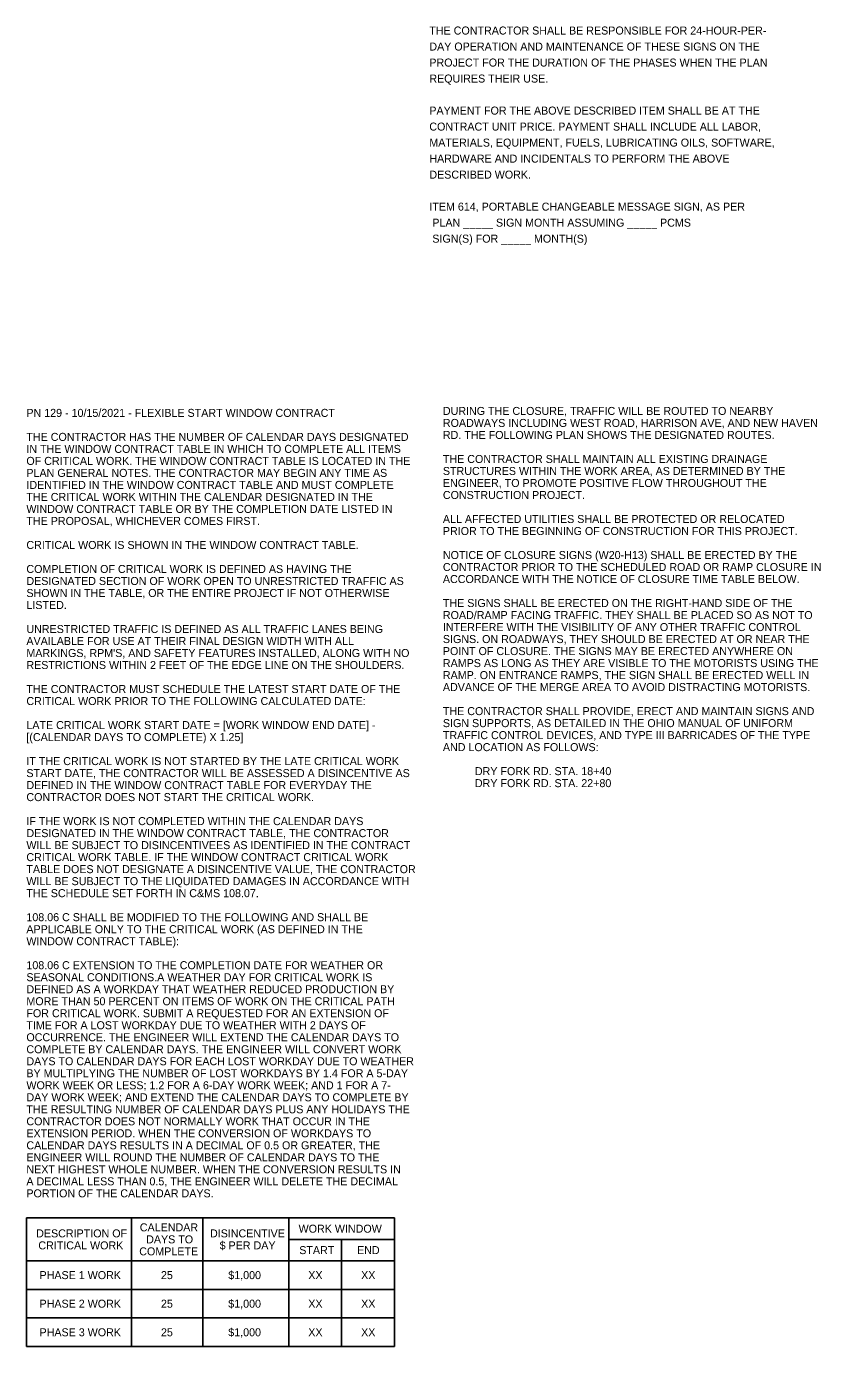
# Model space of a CAD drawing. Extents: x -65.5 to 34, y -24.3 to 23.1.
# Drawn here: x -50.15 to -36.25, y -24.33 to -1.24 of the extents above; entities that cross this region are included whole.
import ezdxf

# ---------------------------------------------------------------- set-up
doc = ezdxf.new("R2010")
doc.units = 0
doc.layers.add('SH_Text', color=7, linetype='Continuous')

msp = doc.modelspace()

# ---------------------------------------------------------------- linework, layer by layer
at = {"layer": 'SH_Text'}
for p, q in [((-50.153, -22.081), (-50.153, -22.831)), ((-48.313, -22.081), (-48.313, -22.831)), ((-47.063, -22.081), (-47.063, -22.831)), ((-45.563, -22.081), (-45.563, -22.831)), ((-43.713, -22.081), (-43.713, -22.831)), ((-45.563, -22.456), (-43.713, -22.456)), ((-44.638, -22.831), (-44.638, -22.456)), ((-50.153, -22.831), (-50.153, -23.331)), ((-48.313, -22.831), (-48.313, -23.331)), ((-47.063, -22.831), (-47.063, -23.331)), ((-45.563, -22.831), (-45.563, -23.331)), ((-44.638, -22.831), (-44.638, -23.331)), ((-43.713, -22.831), (-43.713, -23.331)), ((-50.153, -23.331), (-50.153, -23.831)), ((-48.313, -23.331), (-48.313, -23.831)), ((-47.063, -23.331), (-47.063, -23.831)), ((-45.563, -23.331), (-45.563, -23.831)), ((-44.638, -23.331), (-44.638, -23.831)), ((-43.713, -23.331), (-43.713, -23.831)), ((-50.153, -23.831), (-50.153, -24.331)), ((-48.313, -23.831), (-48.313, -24.331)), ((-47.063, -23.831), (-47.063, -24.331)), ((-45.563, -23.831), (-45.563, -24.331)), ((-44.638, -23.831), (-44.638, -24.331)), ((-43.713, -23.831), (-43.713, -24.331))]:
    msp.add_line(p, q, dxfattribs=at)
for points in [[(-50.153, -22.081), (-48.313, -22.081), (-47.063, -22.081), (-45.563, -22.081), (-43.713, -22.081)], [(-50.153, -22.831), (-48.313, -22.831), (-47.063, -22.831), (-45.563, -22.831), (-44.638, -22.831), (-43.713, -22.831)], [(-50.153, -23.331), (-48.313, -23.331), (-47.063, -23.331), (-45.563, -23.331), (-44.638, -23.331), (-43.713, -23.331)], [(-50.153, -23.831), (-48.313, -23.831), (-47.063, -23.831), (-45.563, -23.831), (-44.638, -23.831), (-43.713, -23.831)], [(-50.153, -24.331), (-48.313, -24.331), (-47.063, -24.331), (-45.563, -24.331), (-44.638, -24.331), (-43.713, -24.331)]]:
    msp.add_lwpolyline(points, dxfattribs=at)

# ---------------------------------------------------------------- texts
for s, p in [('THE CONTRACTOR SHALL BE RESPONSIBLE FOR 24-HOUR-PER-', (-43.101, -1.384)), ('DAY OPERATION AND MAINTENANCE OF THESE SIGNS ON THE', (-43.101, -1.664)), ('PROJECT FOR THE DURATION OF THE PHASES WHEN THE PLAN', (-43.101, -1.944)), ('REQUIRES THEIR USE.', (-43.101, -2.224)), ('PAYMENT FOR THE ABOVE DESCRIBED ITEM SHALL BE AT THE', (-43.101, -2.784)), ('CONTRACT UNIT PRICE. PAYMENT SHALL INCLUDE ALL LABOR,', (-43.101, -3.064)), ('MATERIALS, EQUIPMENT, FUELS, LUBRICATING OILS, SOFTWARE,', (-43.101, -3.344)), ('HARDWARE AND INCIDENTALS TO PERFORM THE ABOVE', (-43.101, -3.624)), ('DESCRIBED WORK.', (-43.101, -3.904)), ('ITEM 614, PORTABLE CHANGEABLE MESSAGE SIGN, AS PER', (-43.101, -4.464)), (' PLAN _____ SIGN MONTH ASSUMING _____ PCMS', (-43.101, -4.744)), (' SIGN(S) FOR _____ MONTH(S)', (-43.101, -5.024)), ('PN 129 - 10/15/2021 - FLEXIBLE START WINDOW CONTRACT', (-50.153, -8.071)), ('DURING THE CLOSURE, TRAFFIC WILL BE ROUTED TO NEARBY ', (-42.864, -8.037)), ('ROADWAYS INCLUDING WEST ROAD, HARRISON AVE, AND NEW HAVEN ', (-42.864, -8.247)), ('THE CONTRACTOR HAS THE NUMBER OF CALENDAR DAYS DESIGNATED ', (-50.153, -8.491)), ('RD. THE FOLLOWING PLAN SHOWS THE DESIGNATED ROUTES. ', (-42.864, -8.457)), ('OF CRITICAL WORK. THE WINDOW CONTRACT TABLE IS LOCATED IN THE ', (-50.153, -8.911)), ('IN THE WINDOW CONTRACT TABLE IN WHICH TO COMPLETE ALL ITEMS ', (-50.153, -8.701)), ('THE CONTRACTOR SHALL MAINTAIN ALL EXISTING DRAINAGE ', (-42.864, -8.877)), ('PLAN GENERAL NOTES. THE CONTRACTOR MAY BEGIN ANY TIME AS ', (-50.153, -9.121)), ('STRUCTURES WITHIN THE WORK AREA, AS DETERMINED BY THE ', (-42.864, -9.087)), ('IDENTIFIED IN THE WINDOW CONTRACT TABLE AND MUST COMPLETE ', (-50.153, -9.331)), ('ENGINEER, TO PROMOTE POSITIVE FLOW THROUGHOUT THE ', (-42.864, -9.297)), ('THE CRITICAL WORK WITHIN THE CALENDAR DESIGNATED IN THE ', (-50.153, -9.541)), ('CONSTRUCTION PROJECT.', (-42.864, -9.507)), ('WINDOW CONTRACT TABLE OR BY THE COMPLETION DATE LISTED IN ', (-50.153, -9.751)), ('THE PROPOSAL, WHICHEVER COMES FIRST.', (-50.153, -9.961)), ('ALL AFFECTED UTILITIES SHALL BE PROTECTED OR RELOCATED ', (-42.864, -9.927)), ('PRIOR TO THE BEGINNING OF CONSTRUCTION FOR THIS PROJECT.', (-42.864, -10.137)), ('CRITICAL WORK IS SHOWN IN THE WINDOW CONTRACT TABLE.', (-50.153, -10.381)), ('NOTICE OF CLOSURE SIGNS (W20-H13) SHALL BE ERECTED BY THE ', (-42.864, -10.557)), ('COMPLETION OF CRITICAL WORK IS DEFINED AS HAVING THE ', (-50.153, -10.801)), ('ACCORDANCE WITH THE NOTICE OF CLOSURE TIME TABLE BELOW.', (-42.864, -10.977)), ('CONTRACTOR PRIOR TO THE SCHEDULED ROAD OR RAMP CLOSURE IN ', (-42.864, -10.767)), ('SHOWN IN THE TABLE, OR THE ENTIRE PROJECT IF NOT OTHERWISE ', (-50.153, -11.221)), ('DESIGNATED SECTION OF WORK OPEN TO UNRESTRICTED TRAFFIC AS ', (-50.153, -11.011)), ('LISTED.', (-50.153, -11.431)), ('THE SIGNS SHALL BE ERECTED ON THE RIGHT-HAND SIDE OF THE ', (-42.864, -11.397)), ('ROAD/RAMP FACING TRAFFIC. THEY SHALL BE PLACED SO AS NOT TO ', (-42.864, -11.607)), ('UNRESTRICTED TRAFFIC IS DEFINED AS ALL TRAFFIC LANES BEING ', (-50.153, -11.851)), ('INTERFERE WITH THE VISIBILITY OF ANY OTHER TRAFFIC CONTROL ', (-42.864, -11.817)), ('AVAILABLE FOR USE AT THEIR FINAL DESIGN WIDTH WITH ALL ', (-50.153, -12.061)), ('SIGNS. ON ROADWAYS, THEY SHOULD BE ERECTED AT OR NEAR THE ', (-42.864, -12.027)), ("MARKINGS, RPM'S, AND SAFETY FEATURES INSTALLED, ALONG WITH NO ", (-50.153, -12.271)), ('POINT OF CLOSURE. THE SIGNS MAY BE ERECTED ANYWHERE ON ', (-42.864, -12.237)), ('RESTRICTIONS WITHIN 2 FEET OF THE EDGE LINE ON THE SHOULDERS.', (-50.153, -12.481)), ('RAMPS AS LONG AS THEY ARE VISIBLE TO THE MOTORISTS USING THE ', (-42.864, -12.447)), ('RAMP. ON ENTRANCE RAMPS, THE SIGN SHALL BE ERECTED WELL IN ', (-42.864, -12.657)), ('THE CONTRACTOR MUST SCHEDULE THE LATEST START DATE OF THE ', (-50.153, -12.901)), ('ADVANCE OF THE MERGE AREA TO AVOID DISTRACTING MOTORISTS.', (-42.864, -12.867)), ('CRITICAL WORK PRIOR TO THE FOLLOWING CALCULATED DATE:', (-50.153, -13.111)), ('THE CONTRACTOR SHALL PROVIDE, ERECT AND MAINTAIN SIGNS AND ', (-42.864, -13.287)), ('LATE CRITICAL WORK START DATE = [WORK WINDOW END DATE] - ', (-50.153, -13.531)), ('SIGN SUPPORTS, AS DETAILED IN THE OHIO MANUAL OF UNIFORM ', (-42.864, -13.497)), ('[(CALENDAR DAYS TO COMPLETE) X 1.25]', (-50.153, -13.741)), ('TRAFFIC CONTROL DEVICES, AND TYPE III BARRICADES OF THE TYPE ', (-42.864, -13.707)), ('AND LOCATION AS FOLLOWS:', (-42.864, -13.917)), ('IT THE CRITICAL WORK IS NOT STARTED BY THE LATE CRITICAL WORK ', (-50.153, -14.161)), ('START DATE, THE CONTRACTOR WILL BE ASSESSED A DISINCENTIVE AS ', (-50.153, -14.371)), ('DRY FORK RD. STA. 18+40', (-42.304, -14.337)), ('DEFINED IN THE WINDOW CONTRACT TABLE FOR EVERYDAY THE ', (-50.153, -14.581)), ('DRY FORK RD. STA. 22+80', (-42.304, -14.547)), ('CONTRACTOR DOES NOT START THE CRITICAL WORK.', (-50.153, -14.791)), ('IF THE WORK IS NOT COMPLETED WITHIN THE CALENDAR DAYS ', (-50.153, -15.211)), ('DESIGNATED IN THE WINDOW CONTRACT TABLE, THE CONTRACTOR ', (-50.153, -15.421)), ('WILL BE SUBJECT TO DISINCENTIVEES AS IDENTIFIED IN THE CONTRACT ', (-50.153, -15.631)), ('CRITICAL WORK TABLE. IF THE WINDOW CONTRACT CRITICAL WORK ', (-50.153, -15.841)), ('TABLE DOES NOT DESIGNATE A DISINCENTIVE VALUE, THE CONTRACTOR ', (-50.153, -16.051)), ('WILL BE SUBJECT TO THE LIQUIDATED DAMAGES IN ACCORDANCE WITH ', (-50.153, -16.261)), ('THE SCHEDULE SET FORTH IN C&MS 108.07.', (-50.153, -16.471)), ('108.06 C SHALL BE MODIFIED TO THE FOLLOWING AND SHALL BE ', (-50.153, -16.891)), ('APPLICABLE ONLY TO THE CRITICAL WORK (AS DEFINED IN THE ', (-50.153, -17.101)), ('WINDOW CONTRACT TABLE):', (-50.153, -17.311)), ('108.06 C EXTENSION TO THE COMPLETION DATE FOR WEATHER OR ', (-50.153, -17.731)), ('SEASONAL CONDITIONS.', (-50.153, -17.941)), ('DEFINED AS A WORKDAY THAT WEATHER REDUCED PRODUCTION BY ', (-50.153, -18.151)), (' A WEATHER DAY FOR CRITICAL WORK IS ', (-47.916, -17.941)), ('MORE THAN 50 PERCENT ON ITEMS OF WORK ON THE CRITICAL PATH ', (-50.153, -18.361)), ('FOR CRITICAL WORK. SUBMIT A REQUESTED FOR AN EXTENSION OF ', (-50.153, -18.571)), ('TIME FOR A LOST WORKDAY DUE TO WEATHER WITH 2 DAYS OF ', (-50.153, -18.781)), ('OCCURRENCE. THE ENGINEER WILL EXTEND THE CALENDAR DAYS TO ', (-50.153, -18.991)), ('COMPLETE BY CALENDAR DAYS. THE ENGINEER WILL CONVERT WORK ', (-50.153, -19.201)), ('DAYS TO CALENDAR DAYS FOR EACH LOST WORKDAY DUE TO WEATHER ', (-50.153, -19.411)), ('BY MULTIPLYING THE NUMBER OF LOST WORKDAYS BY 1.4 FOR A 5-DAY ', (-50.153, -19.621)), ('WORK WEEK OR LESS; 1.2 FOR A 6-DAY WORK WEEK; AND 1 FOR A 7-', (-50.153, -19.831)), ('DAY WORK WEEK; AND EXTEND THE CALENDAR DAYS TO COMPLETE BY ', (-50.153, -20.041)), ('THE RESULTING NUMBER OF CALENDAR DAYS PLUS ANY HOLIDAYS THE ', (-50.153, -20.251)), ('CONTRACTOR DOES NOT NORMALLY WORK THAT OCCUR IN THE ', (-50.153, -20.461)), ('EXTENSION PERIOD. WHEN THE CONVERSION OF WORKDAYS TO ', (-50.153, -20.671)), ('CALENDAR DAYS RESULTS IN A DECIMAL OF 0.5 OR GREATER, THE ', (-50.153, -20.881)), ('ENGINEER WILL ROUND THE NUMBER OF CALENDAR DAYS TO THE ', (-50.153, -21.091)), ('NEXT HIGHEST WHOLE NUMBER. WHEN THE CONVERSION RESULTS IN ', (-50.153, -21.301)), ('A DECIMAL LESS THAN 0.5, THE ENGINEER WILL DELETE THE DECIMAL ', (-50.153, -21.511)), ('PORTION OF THE CALENDAR DAYS.', (-50.153, -21.721)), ('DESCRIPTION OF ', (-49.982, -22.421)), ('CALENDAR ', (-48.168, -22.316)), ('DAYS TO ', (-48.057, -22.526)), ('DISINCENTIVE ', (-46.94, -22.421)), ('WORK WINDOW', (-45.389, -22.339)), ('CRITICAL WORK', (-49.944, -22.631)), ('COMPLETE', (-48.178, -22.736)), ('$ PER DAY', (-46.771, -22.631)), ('START', (-45.378, -22.714)), ('END', (-44.366, -22.714)), ('PHASE 1 WORK', (-49.923, -23.151)), ('25', (-47.798, -23.151)), ('$1,000', (-46.62, -23.151)), ('XX', (-45.22, -23.151)), ('XX', (-44.295, -23.151)), ('PHASE 2 WORK', (-49.923, -23.651)), ('25', (-47.798, -23.651)), ('$1,000', (-46.62, -23.651)), ('XX', (-45.22, -23.651)), ('XX', (-44.295, -23.651)), ('PHASE 3 WORK', (-49.923, -24.151)), ('25', (-47.798, -24.151)), ('$1,000', (-46.62, -24.151)), ('XX', (-45.22, -24.151)), ('XX', (-44.295, -24.151))]:
    msp.add_text(s, height=0.14, dxfattribs=at).set_placement(p)

doc.saveas('drawing.dxf')
